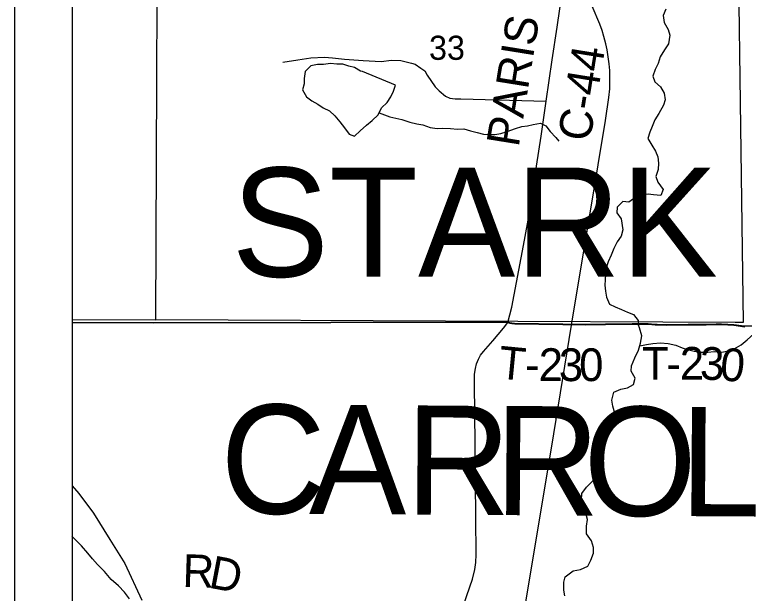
# Model space of a CAD drawing. Extents: x 0 to 34, y 0 to 22.
# Drawn here: x 2 to 3.267, y 16.545 to 17.55 of the extents above; entities that cross this region are included whole.
import ezdxf

# ---------------------------------------------------------------- set-up
doc = ezdxf.new("R2010")
doc.units = 0
for name, color, linetype in [('Default', 7, 'Continuous'), ('SH_Cut_Line', 7, 'Continuous'), ('SH_Data', 7, 'Continuous'), ('SH_Text', 7, 'Continuous')]:
    doc.layers.add(name, color=color, linetype=linetype)

msp = doc.modelspace()

# ---------------------------------------------------------------- linework, layer by layer
at = {"layer": 'Default'}
for points in [[(2.1, 20.9), (2.1, 17.0156), (2.2417, 17.015), (2.8563, 17.0159), (2.8596, 17.0148), (2.8633, 17.0141), (2.8682, 17.0138), (2.9517, 17.0127), (2.9917, 17.0122), (3.0259, 17.0124), (3.0724, 17.0133), (3.0961, 17.0133), (3.1001, 17.0131), (3.1119, 17.0118), (3.1137, 17.0117), (3.1157, 17.0118), (3.1313, 17.0114), (3.1693, 17.0117), (3.1864, 17.0119), (3.1943, 17.0118), (3.2007, 17.012), (3.2183, 17.0125), (3.2227, 17.0124), (3.2272, 17.0123), (3.2383, 17.0121), (3.2487, 17.0113), (3.262, 17.0094), (3.2649, 17.0089), (3.5555, 17.0115)], [(2.8565, 17.0154), (2.8631, 17.0421), (2.8838, 17.1491), (2.8944, 17.2089), (2.9064, 17.2865), (2.9142, 17.3387), (2.9228, 17.3994), (2.9334, 17.4712), (2.9418, 17.5282), (2.9514, 17.5924), (2.9565, 17.6309), (2.9575, 17.6514), (2.9591, 17.6906), (2.9608, 17.7489), (2.9624, 17.8361), (2.9641, 17.8959), (2.9654, 17.9495), (2.9665, 17.9898)], [(2.9672, 17.0108), (3.0132, 17.2889), (3.0258, 17.366), (3.0318, 17.4059), (3.0333, 17.4211), (3.0338, 17.4357), (3.0333, 17.4528), (3.0323, 17.4643), (3.0308, 17.4764), (3.0288, 17.4885), (3.0265, 17.4992), (3.023, 17.5117), (3.02, 17.5219), (3.0159, 17.5333), (3.0031, 17.5646)], [(3.1308, 17.5594), (3.126, 17.5479), (3.1281, 17.5358), (3.135, 17.5241), (3.1378, 17.5139), (3.1353, 17.4991), (3.1282, 17.4888), (3.1208, 17.4762), (3.1176, 17.4648), (3.1124, 17.4545), (3.1084, 17.4427), (3.1119, 17.4328), (3.1215, 17.4246), (3.1276, 17.4136), (3.1297, 17.4019), (3.1268, 17.3924), (3.1186, 17.3779), (3.1116, 17.3672), (3.1072, 17.3554), (3.1027, 17.3458), (3.0995, 17.3348), (3.1064, 17.3231), (3.113, 17.3126), (3.1169, 17.3027), (3.1178, 17.2921), (3.1175, 17.2807), (3.1135, 17.2689), (3.117, 17.2587), (3.1263, 17.2463), (3.1219, 17.2356), (3.1094, 17.237), (3.0999, 17.2384), (3.0882, 17.2368), (3.0784, 17.2329), (3.0664, 17.2244), (3.0558, 17.2251), (3.046, 17.2155), (3.0454, 17.2056), (3.0531, 17.1955), (3.056, 17.1762), (3.0531, 17.1651), (3.0464, 17.1552), (3.0405, 17.1437), (3.0361, 17.1323), (3.0305, 17.1209), (3.0269, 17.1102), (3.0259, 17.0992), (3.0256, 17.0897), (3.025, 17.0802), (3.0259, 17.07), (3.0275, 17.0594), (3.0329, 17.0473), (3.0425, 17.0428), (3.0535, 17.038), (3.0641, 17.0336), (3.0748, 17.0291), (3.0829, 17.0189), (3.0832, 17.0106)], [(2.4655, 17.467), (2.4919, 17.4714), (2.5146, 17.4749), (2.5378, 17.4761), (2.5521, 17.4746), (2.5726, 17.4721), (2.6054, 17.4702), (2.6367, 17.4684), (2.6547, 17.4704), (2.6707, 17.4702), (2.689, 17.4657), (2.6956, 17.4638), (2.7055, 17.4569), (2.7122, 17.4519), (2.7163, 17.4448), (2.7304, 17.4241), (2.7371, 17.4174), (2.7479, 17.408), (2.7558, 17.4048), (2.7649, 17.4036), (2.7748, 17.4033), (2.9228, 17.3994)], [(2.6041, 17.4507), (2.6007, 17.4514), (2.59, 17.4578), (2.5805, 17.46), (2.5699, 17.4636), (2.5597, 17.4639), (2.5487, 17.4649), (2.5366, 17.4629), (2.526, 17.4632), (2.5143, 17.4608), (2.5045, 17.4508), (2.5028, 17.439), (2.5029, 17.4296), (2.5, 17.4193), (2.5066, 17.4068), (2.5161, 17.4001), (2.5264, 17.3941), (2.536, 17.3878), (2.5466, 17.3826), (2.5562, 17.374), (2.565, 17.3638), (2.5727, 17.3533), (2.5808, 17.3423), (2.5903, 17.339), (2.6001, 17.3479), (2.6113, 17.3578), (2.621, 17.3659), (2.6311, 17.3755), (2.637, 17.3877), (2.6468, 17.3973), (2.6531, 17.4072), (2.6579, 17.4171), (2.6612, 17.4274)], [(2.6612, 17.4274), (2.6041, 17.4507)], [(2.633, 17.3794), (2.6516, 17.3723), (2.6622, 17.3698), (2.6721, 17.3676), (2.6862, 17.3628), (2.6983, 17.3599), (2.7086, 17.3585), (2.7215, 17.354), (2.7336, 17.3519), (2.7438, 17.3528), (2.7567, 17.3518), (2.7692, 17.3511), (2.7802, 17.3516), (2.7916, 17.3483), (2.8033, 17.3454), (2.814, 17.3425), (2.8235, 17.3414), (2.8337, 17.3415), (2.8442, 17.3432), (2.8552, 17.3471), (2.8695, 17.3522), (2.8808, 17.3553), (2.8906, 17.3569), (2.9005, 17.3589), (2.9129, 17.3613), (2.9224, 17.3565), (2.9298, 17.3467), (2.9397, 17.3362), (2.9447, 17.3302)], [(3.5555, 17.0115), (3.2649, 17.0089), (3.262, 17.0094), (3.2487, 17.0113), (3.2383, 17.0121), (3.2272, 17.0123), (3.2227, 17.0124), (3.2183, 17.0125), (3.2007, 17.012), (3.1943, 17.0118), (3.1864, 17.0119), (3.1693, 17.0117), (3.1313, 17.0114), (3.1157, 17.0118), (3.1137, 17.0117), (3.1119, 17.0118), (3.1001, 17.0131), (3.0961, 17.0133), (3.0724, 17.0133), (3.0259, 17.0124), (2.9917, 17.0122), (2.9517, 17.0127), (2.8682, 17.0138), (2.8633, 17.0141), (2.8596, 17.0148), (2.8563, 17.0159), (2.2417, 17.015), (2.1, 17.0156), (2.1, 14.1)], [(2.7536, 16.3903), (2.7572, 16.4197), (2.7633, 16.4531), (2.77, 16.4862), (2.7773, 16.5171), (2.7854, 16.5419), (2.7952, 16.5699), (2.7994, 16.5866), (2.801, 16.5991), (2.8016, 16.6128), (2.8007, 16.6763), (2.7997, 16.8054), (2.7985, 16.9091), (2.7987, 16.9258), (2.8, 16.9356), (2.8021, 16.9437), (2.8053, 16.952), (2.8092, 16.9585), (2.8142, 16.9649), (2.8306, 16.9836), (2.8489, 17.0057), (2.8565, 17.0154)], [(2.8565, 17.0154), (2.8598, 17.0142), (2.8635, 17.0136), (2.8684, 17.0132), (2.9519, 17.0121), (2.9919, 17.0116), (3.0261, 17.0118), (3.0528, 17.0124)], [(2.887, 16.5264), (2.936, 16.8224), (2.9672, 17.0108)], [(3.0382, 16.8425), (3.0425, 16.8558), (3.0389, 16.8702), (3.0368, 16.8807), (3.0407, 16.8948), (3.0527, 16.8999), (3.064, 16.902), (3.0745, 16.9079), (3.0774, 16.9189), (3.0704, 16.9309), (3.0713, 16.9404), (3.0772, 16.9542), (3.0834, 16.9672), (3.0866, 16.9797), (3.089, 16.9923), (3.085, 17.0059), (3.0832, 17.0106)], [(3.0528, 17.0124), (3.0726, 17.0128), (3.0963, 17.0128), (3.1003, 17.0125), (3.1121, 17.0113), (3.1139, 17.0111), (3.1159, 17.0112), (3.1315, 17.0109), (3.1695, 17.0112), (3.1866, 17.0113), (3.1945, 17.0113), (3.2009, 17.0114), (3.2185, 17.012), (3.2229, 17.0119), (3.2274, 17.0117), (3.2385, 17.0116), (3.2489, 17.0107), (3.268, 17.008)], [(3.0854, 16.975), (3.0972, 16.9772), (3.1081, 16.9789), (3.1217, 16.9803), (3.135, 16.979), (3.1482, 16.9758), (3.1589, 16.9714), (3.1684, 16.9685), (3.1801, 16.9657), (3.1904, 16.964), (3.2036, 16.9638), (3.2149, 16.9648), (3.2282, 16.9642), (3.2387, 16.9663), (3.2496, 16.9699), (3.2616, 16.9765), (3.2717, 16.9854), (3.2895, 17.0012), (3.298, 17.0095)], [(2.9555, 16.5409), (2.9538, 16.5511), (2.9536, 16.5647), (2.9561, 16.5743), (2.9699, 16.5843), (2.9827, 16.5868), (2.9955, 16.5927), (3.0006, 16.6027), (3.0049, 16.6149), (3.0051, 16.6247), (3.0015, 16.6368), (2.993, 16.6484), (2.9928, 16.6617), (2.9949, 16.6738), (2.9913, 16.6867), (2.9881, 16.6965), (2.9845, 16.707), (2.9851, 16.7184), (2.9932, 16.7299), (3.0055, 16.7422), (3.0117, 16.7533), (3.0172, 16.7659), (3.0215, 16.7796), (3.0231, 16.7929), (3.0233, 16.8066), (3.0238, 16.8214), (3.027, 16.8309), (3.0382, 16.8425)], [(2.1, 16.7319), (2.1118, 16.7185), (2.1371, 16.6845), (2.1653, 16.6387), (2.1912, 16.597), (2.2208, 16.5334)], [(2.1997, 16.5361), (2.1908, 16.5477), (2.1804, 16.5582), (2.1678, 16.5697), (2.1562, 16.5832), (2.1439, 16.5955), (2.1354, 16.6052), (2.1273, 16.6149), (2.1161, 16.6276), (2.1019, 16.6422), (2.1, 16.6446)]]:
    msp.add_lwpolyline(points, dxfattribs=at)
for points in [[(2.1, 17.9963), (2.1, 17.0206), (2.2452, 17.0203), (2.2493, 17.9947)], [(2.2493, 17.9947), (3.2516, 17.9922), (3.265, 17.0154), (3.251, 17.0155), (2.2452, 17.0203)]]:
    msp.add_lwpolyline(points, close=True, dxfattribs=at)
at = {"layer": 'SH_Cut_Line'}
for points in [[(2.1, 20.9), (2.1, 17.0156), (2.2417, 17.015), (2.8563, 17.0159), (2.8596, 17.0148), (2.8633, 17.0141), (2.8682, 17.0138), (2.9517, 17.0127), (2.9917, 17.0122), (3.0259, 17.0124), (3.0724, 17.0133), (3.0961, 17.0133), (3.1001, 17.0131), (3.1119, 17.0118), (3.1137, 17.0117), (3.1157, 17.0118), (3.1313, 17.0114), (3.1693, 17.0117), (3.1864, 17.0119), (3.1943, 17.0118), (3.2007, 17.012), (3.2183, 17.0125), (3.2227, 17.0124), (3.2272, 17.0123), (3.2383, 17.0121), (3.2487, 17.0113), (3.262, 17.0094), (3.2649, 17.0089), (3.5555, 17.0115)], [(3.5555, 17.0115), (3.2649, 17.0089), (3.262, 17.0094), (3.2487, 17.0113), (3.2383, 17.0121), (3.2272, 17.0123), (3.2227, 17.0124), (3.2183, 17.0125), (3.2007, 17.012), (3.1943, 17.0118), (3.1864, 17.0119), (3.1693, 17.0117), (3.1313, 17.0114), (3.1157, 17.0118), (3.1137, 17.0117), (3.1119, 17.0118), (3.1001, 17.0131), (3.0961, 17.0133), (3.0724, 17.0133), (3.0259, 17.0124), (2.9917, 17.0122), (2.9517, 17.0127), (2.8682, 17.0138), (2.8633, 17.0141), (2.8596, 17.0148), (2.8563, 17.0159), (2.2417, 17.015), (2.1, 17.0156), (2.1, 14.1)]]:
    msp.add_lwpolyline(points, dxfattribs=at)
at = {"layer": 'SH_Data'}
for p, q in [((2, 21), (2, 14)), ((2.1, 20.9), (2.1, 14.1))]:
    msp.add_line(p, q, dxfattribs=at)

# ---------------------------------------------------------------- texts
at = {"layer": 'Default'}
for s, height, rotation, p in [('PARIS', 0.05682, 80.8475, (2.8751, 17.3184)), ('33', 0.04186, 0, (2.7196, 17.4712)), ('C-44', 0.05682, 80.8177, (2.999, 17.3277)), ('T', 0.0568, 354.4676, (2.8383, 16.9185)), ('2', 0.0568, 359.6878, (2.9098, 16.914)), ('3', 0.0568, 359.7123, (2.9448, 16.9138)), ('0', 0.0568, 0.0769, (2.9802, 16.9137)), ('T', 0.0568, 359.9422, (3.0893, 16.9161)), ('2', 0.0568, 0.1911, (3.1551, 16.9161)), ('3', 0.0568, 358.9905, (3.1896, 16.9162)), ('0', 0.0568, 354.4596, (3.2231, 16.9157)), ('-', 0.0568, 359.9371, (2.8865, 16.9141)), ('-', 0.0568, 0.0806, (3.1319, 16.9161)), ('C', 0.1894, 359.6691, (2.3567, 16.6841)), ('A', 0.1894, 359.6701, (2.5111, 16.6832)), ('R', 0.1894, 359.6691, (2.6783, 16.6822)), ('R', 0.1894, 359.6695, (2.8327, 16.6813)), ('O', 0.1894, 359.6699, (2.9871, 16.6804)), ('L', 0.1894, 359.6706, (3.1543, 16.6795)), ('R', 0.0568, 358.2434, (2.291, 16.5567)), ('D', 0.0568, 349.1823, (2.3352, 16.5556))]:
    msp.add_text(s, height=height, rotation=rotation, dxfattribs=at).set_placement(p)
at = {"layer": 'SH_Text'}
msp.add_text('STARK COUNTY', height=0.1894, dxfattribs=at).set_placement((2.3768, 17.0948))

doc.saveas('drawing.dxf')
